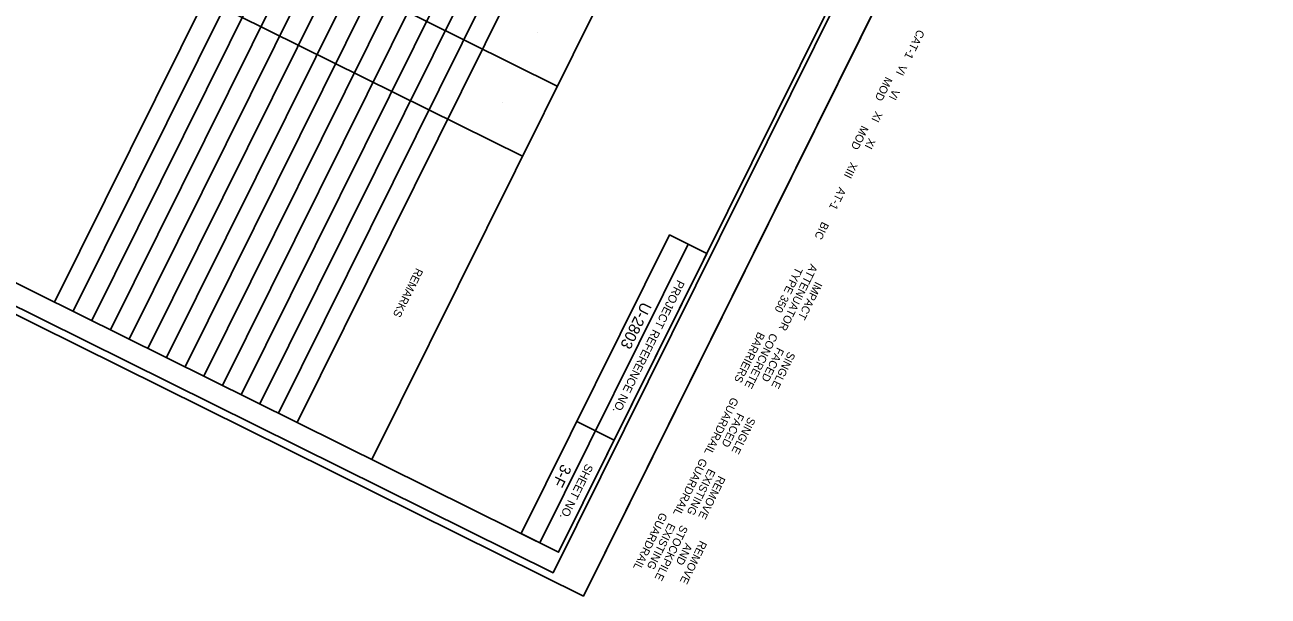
# Model space of a CAD drawing. Extents: x 2112338 to 2116552, y 435818 to 439065.
# Drawn here: x 2113974 to 2114719, y 436578 to 436921 of the extents above; entities that cross this region are included whole.
import ezdxf

# ---------------------------------------------------------------- set-up
doc = ezdxf.new("R2010")
doc.units = 0
for name, color, linetype in [('Sheet Cutting Line CELL', 7, 'Continuous'), ('Sheet Data Field CELL', 7, 'Continuous'), ('Sheet Plot Border Inside CELL', 7, 'Continuous'), ('Sheet Plot Border Outside CELL', 7, 'Continuous'), ('Sheet Summary Guardrail CELL', 7, 'Continuous')]:
    doc.layers.add(name, color=color, linetype=linetype)

msp = doc.modelspace()

# ---------------------------------------------------------------- linework, layer by layer
at = {"layer": 'Sheet Cutting Line CELL'}
msp.add_line((2114308.82, 436578.23), (2115057.49, 438086.66), dxfattribs=at)
at = {"layer": 'Sheet Plot Border Inside CELL'}
msp.add_lwpolyline([(2114086.5, 438554.06), (2113345.61, 437061.31), (2114290.71, 436592.24), (2115031.6, 438084.99)], close=True, dxfattribs=at)
at = {"layer": 'Sheet Plot Border Outside CELL'}
msp.add_lwpolyline([(2114072.17, 438575.69), (2113323.5, 437067.26), (2114308.82, 436578.23), (2115057.49, 438086.66)], close=True, dxfattribs=at)
at = {"layer": 'Sheet Summary Guardrail CELL'}
for p, q in [((2114658.54, 438098.23), (2113991.67, 436754.61)), ((2114669.73, 438092.67), (2114002.87, 436749.06)), ((2114680.93, 438087.11), (2114014.06, 436743.5)), ((2114692.13, 438081.55), (2114025.26, 436737.94)), ((2114703.32, 438076), (2114036.46, 436732.39)), ((2114714.52, 438070.44), (2114047.66, 436726.83)), ((2114725.72, 438064.88), (2114058.85, 436721.27)), ((2114736.91, 438059.33), (2114070.05, 436715.71)), ((2114748.11, 438053.77), (2114081.25, 436710.16)), ((2114759.31, 438048.21), (2114092.44, 436704.6)), ((2114770.5, 438042.65), (2114103.64, 436699.04)), ((2114781.7, 438037.1), (2114114.84, 436693.49)), ((2114792.9, 438031.54), (2114126.03, 436687.93)), ((2114804.09, 438025.98), (2114137.23, 436682.37)), ((2114848.88, 438003.75), (2114182.02, 436660.14)), ((2114293.2, 436884.17), (2114102.86, 436978.64)), ((2114272.31, 436842.07), (2114081.96, 436936.54)), ((2114281.26, 436916.33), (2114281.26, 436916.33)), ((2114260.36, 436874.23), (2114260.36, 436874.23)), ((2114371.68, 436789.34), (2114282.74, 436610.15)), ((2114327.28, 436671.77), (2114304.89, 436682.89))]:
    msp.add_line(p, q, dxfattribs=at)
for points in [[(2114293.98, 436604.57), (2114960.85, 437948.18), (2114020.32, 438414.99), (2113353.46, 437071.37)], [(2114382.92, 436783.76), (2114293.98, 436604.57), (2114271.55, 436615.71), (2114360.48, 436794.9)]]:
    msp.add_lwpolyline(points, close=True, dxfattribs=at)

# ---------------------------------------------------------------- texts
at = {"layer": 'Sheet Data Field CELL'}
for s, p in [('U-2803', (2114343.94, 436755.15)), ('3-F', (2114296.01, 436657.9))]:
    msp.add_text(s, height=6.75, rotation=243.60379, dxfattribs=at).set_placement(p)
at = {"layer": 'Sheet Summary Guardrail CELL'}
for s, height, p in [('CAT-1', 4.8, (2114509.38, 436918.43)), ('VI', 4.8, (2114498.82, 436897.38)), ('MOD', 4.8, (2114490.12, 436890.09)), ('VI', 4.8, (2114494.48, 436882.68)), ('XI', 4.8, (2114484.08, 436869.37)), ('MOD', 4.8, (2114475.72, 436860.85)), ('XI', 4.8, (2114480.01, 436853.3)), ('XIII', 4.8, (2114469.18, 436838.91)), ('AT-1', 4.8, (2114462.21, 436823.84)), ('BIC', 4.8, (2114452, 436803.17)), ('ATTENUATOR', 4.8, (2114445.21, 436777.8)), ('REMARKS', 4.8, (2114208.62, 436775.38)), ('TYPE 350', 4.8, (2114436.27, 436775.98)), ('PROJECT REFERENCE NO.', 5.0001, (2114365.3, 436768.28)), ('IMPACT', 4.8, (2114448, 436767.21)), ('BARRIERS', 4.8, (2114413.63, 436737.1)), ('CONCRETE', 4.8, (2114421.32, 436736.4)), ('FACED', 4.8, (2114425.06, 436727.74)), ('SINGLE', 4.8, (2114431.86, 436725.26)), ('GUARDRAIL', 4.8, (2114397.8, 436697.9)), ('FACED', 4.8, (2114401.18, 436688.52)), ('SINGLE', 4.8, (2114407.99, 436686.03)), ('SHEET NO.', 5, (2114310.46, 436658.02)), ('GUARDRAIL', 4.8, (2114379.1, 436661.35)), ('EXISTING', 4.8, (2114383.99, 436655.01)), ('REMOVE', 4.8, (2114389.95, 436650.83)), ('GUARDRAIL', 4.8, (2114355.14, 436628.81)), ('EXISTING', 4.8, (2114360.03, 436622.47)), ('STOCKPILE', 4.8, (2114367.43, 436621.2)), ('AND', 4.8, (2114370.13, 436610.43)), ('REMOVE', 4.8, (2114378.89, 436611.89))]:
    msp.add_text(s, height=height, rotation=243.60379, dxfattribs=at).set_placement(p)

doc.saveas('drawing.dxf')
